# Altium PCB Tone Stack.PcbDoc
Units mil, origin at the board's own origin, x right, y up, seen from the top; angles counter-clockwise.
Board outline 3400 x 3400 mil, 2 copper layers (Top Layer, Bottom Layer); 39 components, 19 nets, 129 pads, 5 vias.
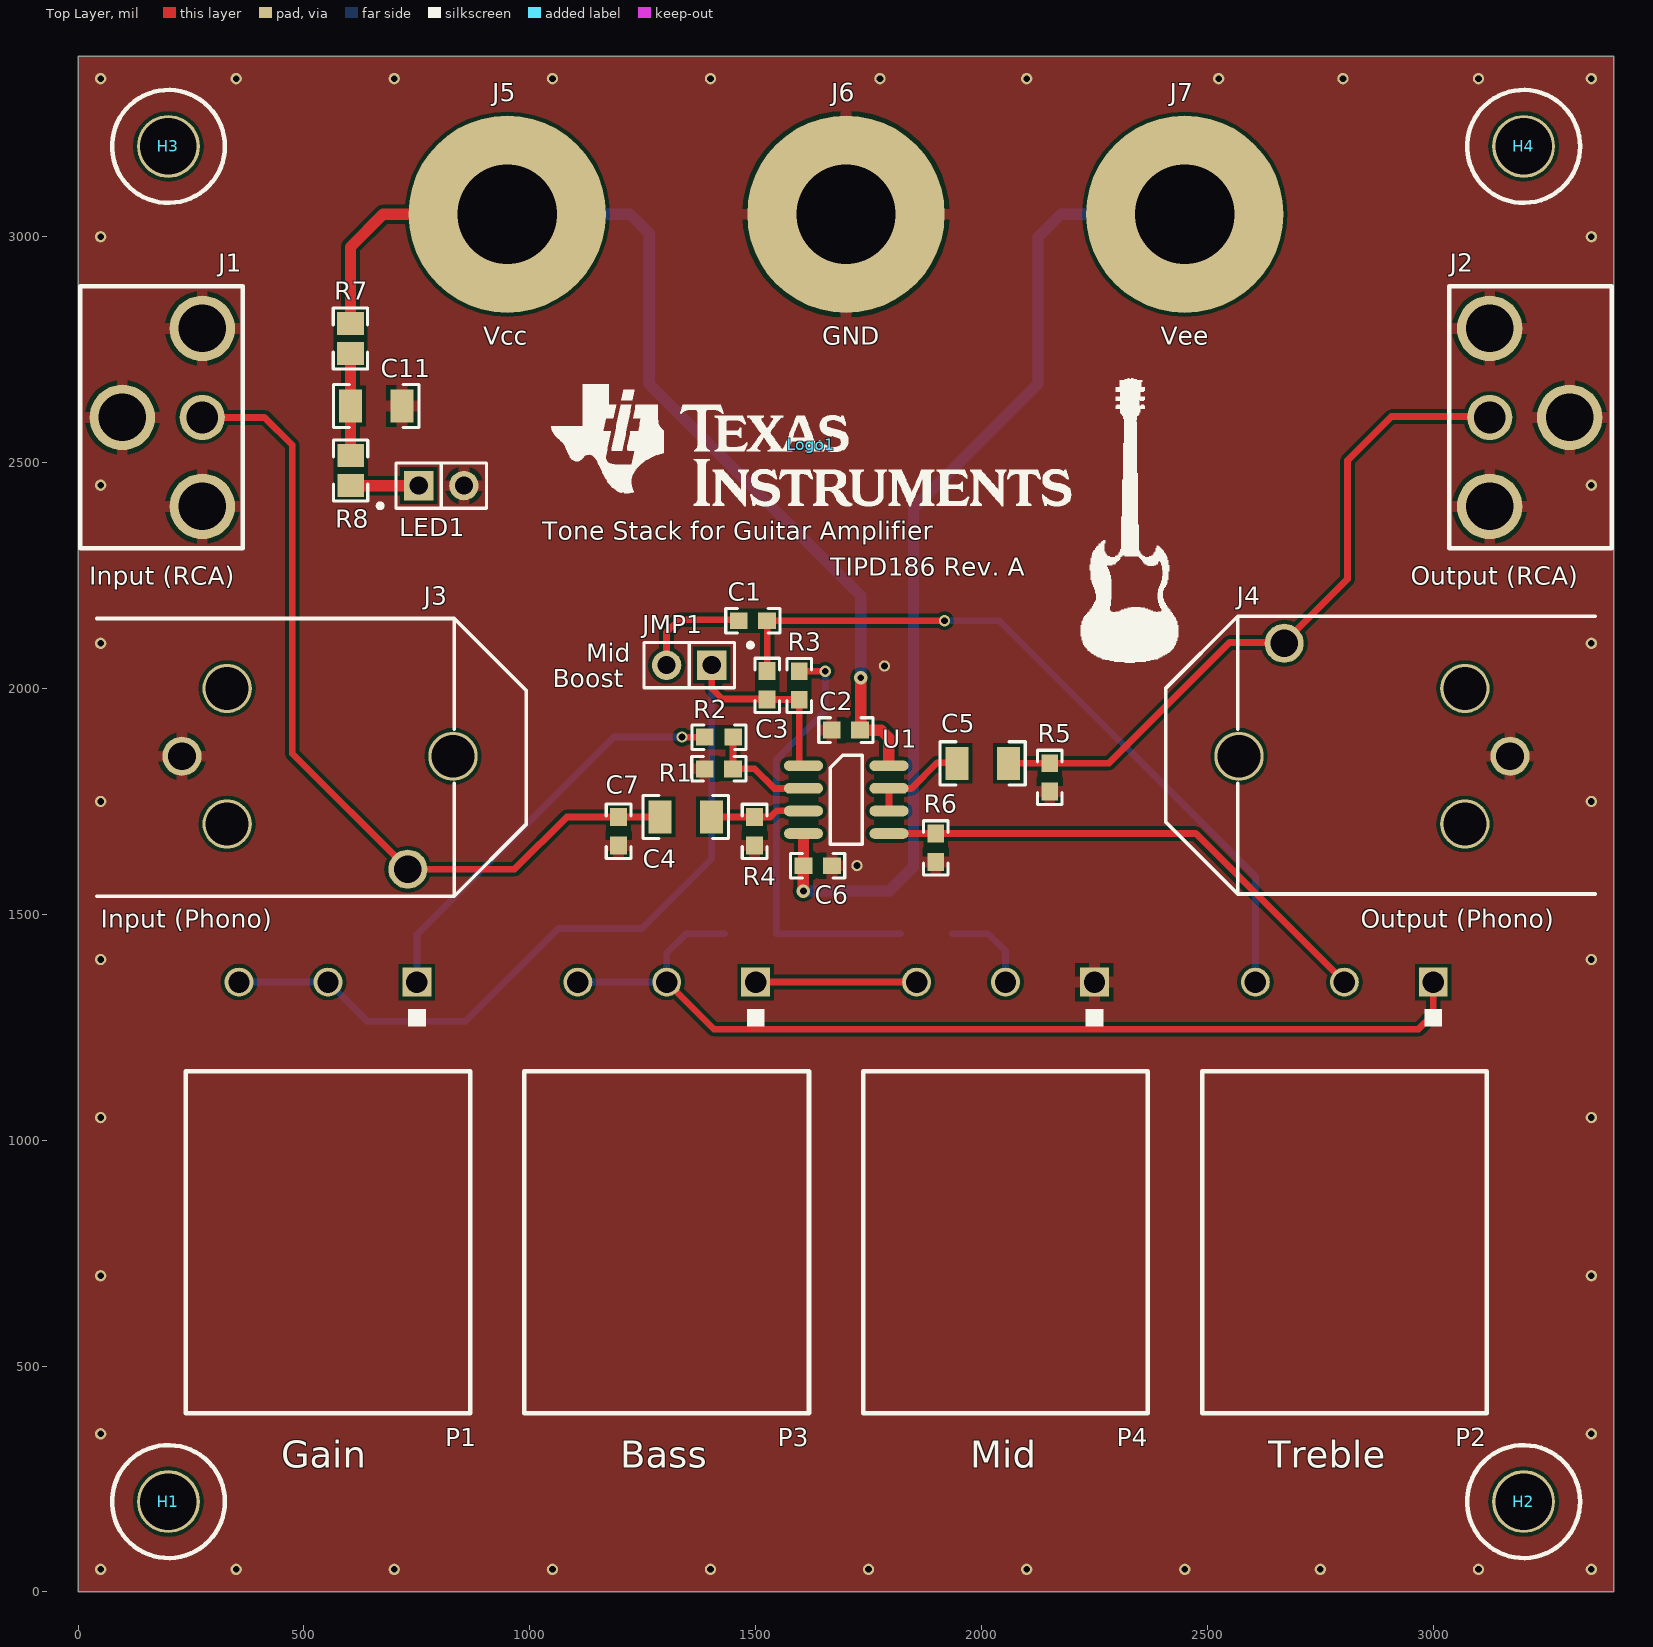
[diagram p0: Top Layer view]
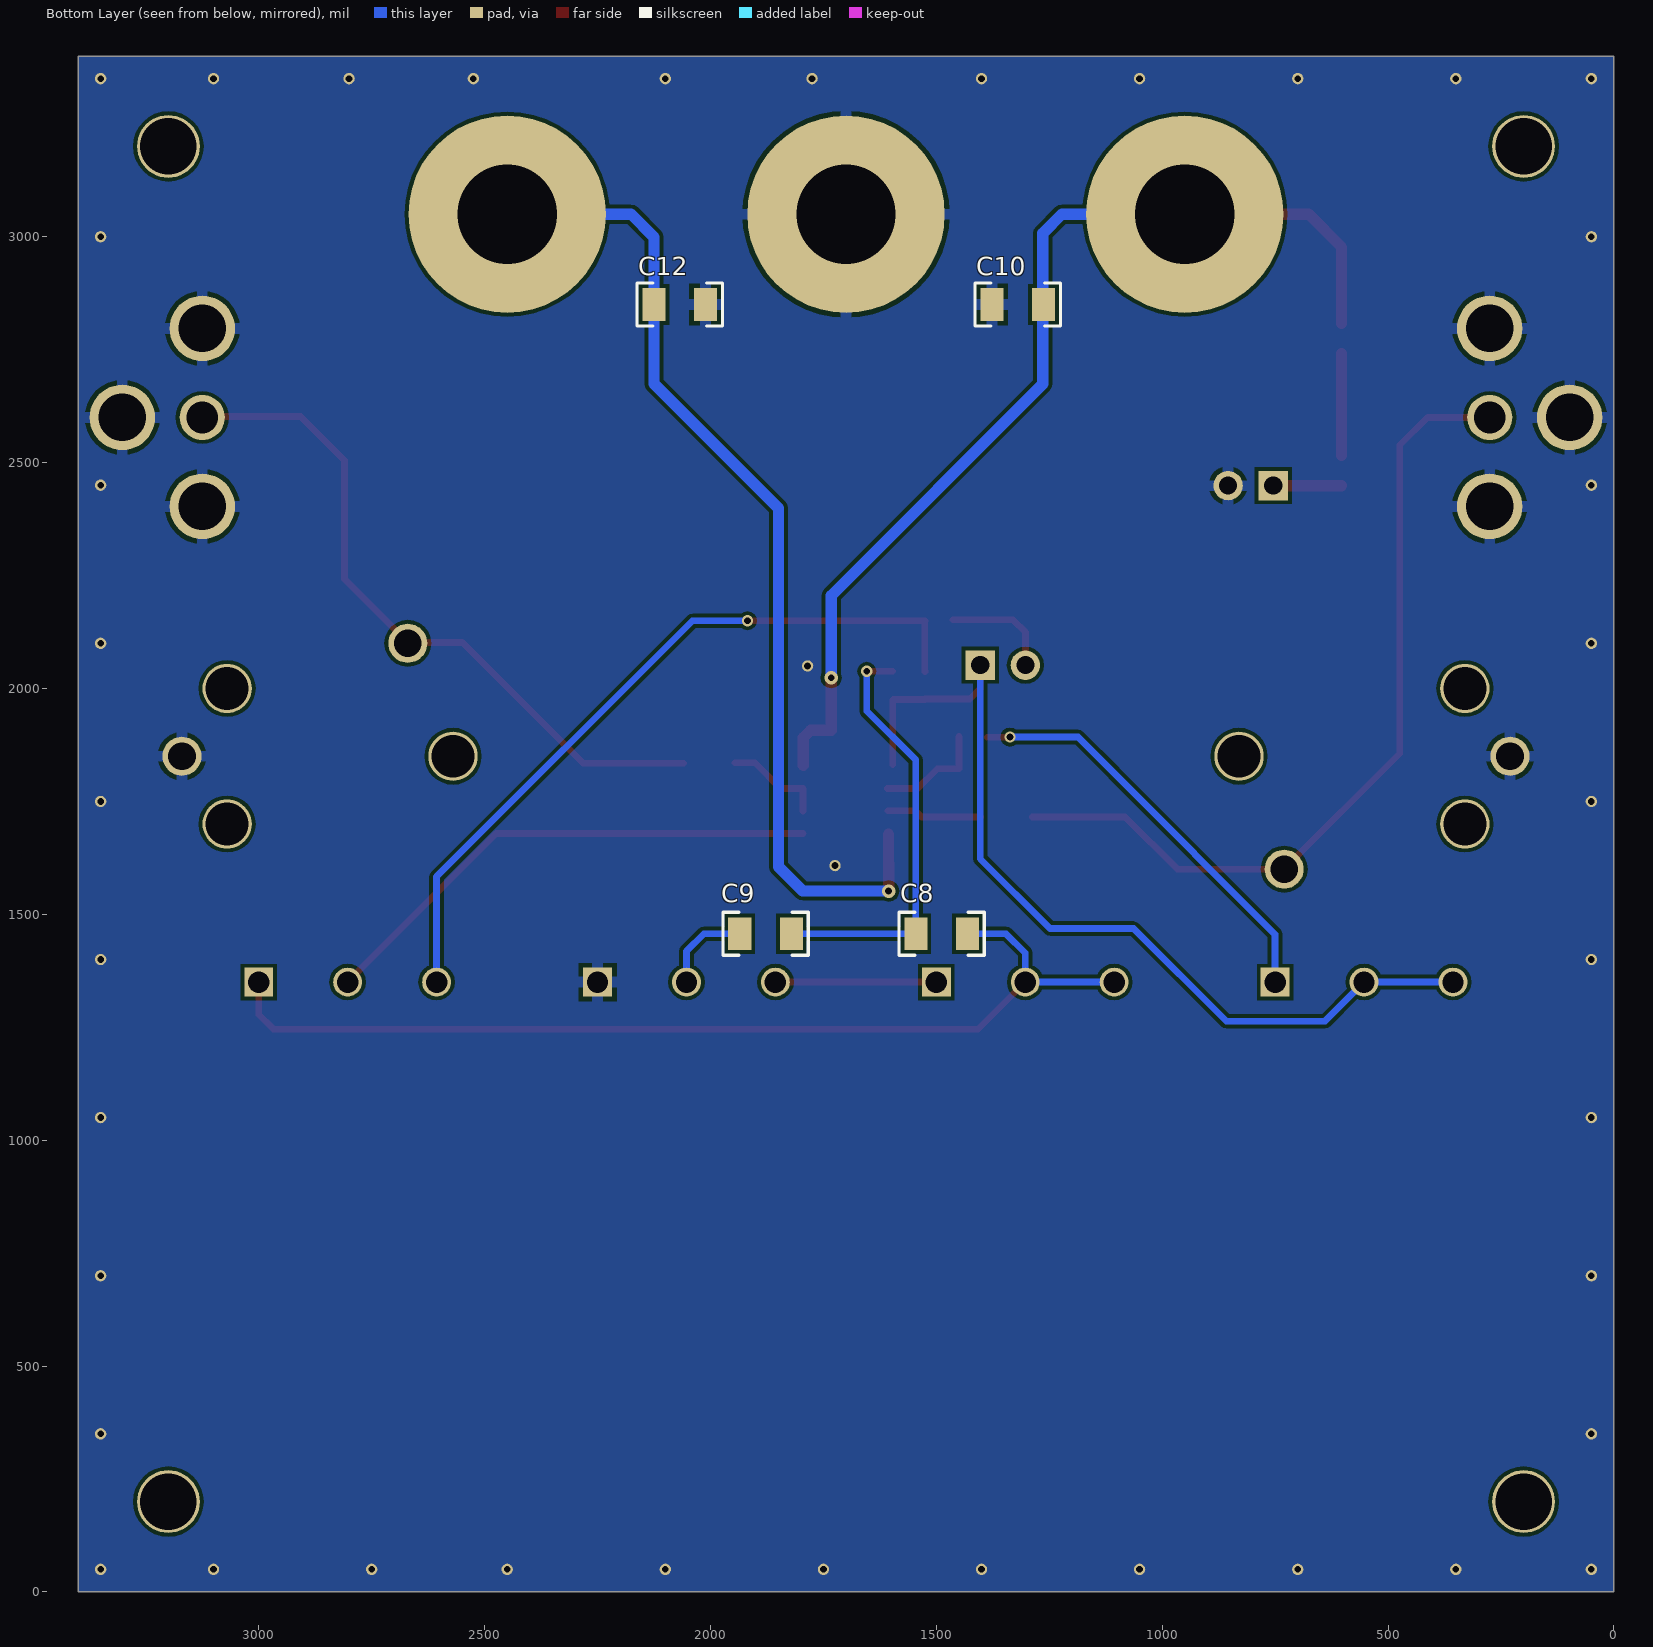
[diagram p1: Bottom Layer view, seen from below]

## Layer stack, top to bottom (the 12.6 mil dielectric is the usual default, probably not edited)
Top Layer: signal copper 1.4
Dielectric: core 12.6, FR-4, Dk 4.8
Bottom Layer: signal copper 1.4

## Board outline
0,0 0,3400 3400,3400 3400,0

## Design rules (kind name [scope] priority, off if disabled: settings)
AssemblyTestPointUsage [All] p1 off:
AssemblyTestpoint [All] p1 off: testpointundercomponent=TRUE minsize=40 maxsize=100 preferedsize=60 minholesize=0 maxholesize=40 preferedholesize=32 testpointgrid=1 usegrid=TRUE gridtolerance=0.01 allowsidetop=TRUE allowsidebottom=TRUE
Clearance [All] p1: gap=8
ComponentClearance [All] p1 off: gap=10 collisioncheckmode=3 verticalgap=10 showdistances=FALSE
DiffPairsRouting [All] p1 off: maxlimit=10 minlimit=10 mostfreqgap=10 maxuncoupledlength=500
FabricationTestPointUsage TestPointUsage [All] p1 off: valid=0 allowmultiple=FALSE
FabricationTestpoint Testpoint [All] p1 off: side=3 testpointundercomponent=TRUE minsize=40 maxsize=100 preferedsize=60 minholesize=0 maxholesize=40 preferedholesize=32 testpointgrid=1 allowsidetop=TRUE allowsidebottom=TRUE usegrid=TRUE gridtolerance=0.01
FanoutControl Fanout_BGA [IsBGA] p1 off: bgadir=Out bgaviamode=Centered fanoutstyle=Auto fanoutdirection=Alternating viagrid=1 // Fanout_BGA (Default Rule)
FanoutControl Fanout_LCC [IsLCC] p2 off: bgadir=Out bgaviamode=Centered fanoutstyle=Auto fanoutdirection=Alternating viagrid=1 // Fanout_LCC (Default Rule)
FanoutControl Fanout_SOIC [IsSOIC] p3 off: bgadir=Out bgaviamode=Centered fanoutstyle=Auto fanoutdirection=Alternating viagrid=1 // Fanout_SOIC (Default Rule)
FanoutControl Fanout_Small [(CompPinCount < 5)] p4 off: bgadir=Out bgaviamode=Centered fanoutstyle=Auto fanoutdirection=OutThenIn viagrid=1 // Fanout_Small (Default Rule)
FanoutControl Fanout_Default [All] p5 off: bgadir=Out bgaviamode=Centered fanoutstyle=Auto fanoutdirection=Alternating viagrid=1 // Fanout_Default (Default Rule)
Height [All] p1 off: minheight=0 maxheight=1000 prefheight=500
HoleSize [All] p1: absolutevalues=TRUE maxlimit=400 minlimit=15 maxpercent=80.000 minpercent=20.000
HoleToHoleClearance [All] p1: gap=7 allowstackedmicrovias=TRUE
MinimumAnnularRing [All] p1: minimumring=5
MinimumSolderMaskSliver [All] p1: minsoldermaskwidth=5
NetAntennae [All] p1 off: netantennaetolerance=0
PolygonConnect "GND Vias" [(InNet('GND') AND InPadClass('GND Vias'))] p1: connectstyle=Direct reliefconductorwidth=10 reliefentries=4 polygonreliefangle="90 Angle" airgapwidth=10
PolygonConnect [All] p2: connectstyle=Relief reliefconductorwidth=25 reliefentries=4 polygonreliefangle="90 Angle" airgapwidth=10
RoutingVias [All] p1: holewidth=10 width=25 viastyle="Through Hole" minholewidth=10 minwidth=25 maxholewidth=400 maxwidth=500
SilkToSilkClearance [All] p1: silktosilkclearance=5
SilkscreenOverComponentPads [All] p1: minsilkscreentomaskgap=5
SolderMaskExpansion [All] p1: expansion=4
Width [All] p1: maxlimit=100 minlimit=8 preferedwidth=15
10 further rules are at their usual default settings.

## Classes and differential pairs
pad class "GND Vias": Free-0
component class "Tone Stack": C1 C2 C3 C4 C5 C6 C7 C8 C9 C11 C12 H1 H2 H3 H4 J1 J2 J3 J4 J5 J6 J7 LED1 Logo1 P1 P2 P3 P4 R1 R2 R3 R4 R5 R6 R8 U1

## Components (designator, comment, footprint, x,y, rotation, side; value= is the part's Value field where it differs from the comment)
C1 "Used in BOM report" 0603 1493.9,2150 r0 top
C2 "Used in BOM report" 0603 1699.73,1907.86 r180 top
C3 "Used in BOM report" 0603 1525.45,2006.96 r90 top
C4 "Used in BOM report" 1206 1345.21,1715.66 r180 top
C5 "Used in BOM report" 1206 2002.47,1834.31 r180 top
C6 "Used in BOM report" 0603 1637.39,1607.67 r0 top
C7 "Used in BOM report" 0603 1196.48,1683.96 r270 top
C8 "Used in BOM report" 1206 1488.37,1457 r180 bottom
C9 "Used in BOM report" 1206 1878.12,1457 r0 bottom
C10 "Used in BOM report" 1206 1319.89,2850 r0 bottom
C11 "Used in BOM report" 1206 660.3,2625.39 r0 top
C12 "Used in BOM report" 1206 2067.98,2850 r0 bottom
H1 "Standoff, 1\", 4-40, Alum, F-F" "STANDOFF HEX 4-40THR ALUM 1\"L" 200,200 r0 top
H2 "Standoff, 1\", 4-40, Alum, F-F" "STANDOFF HEX 4-40THR ALUM 1\"L" 3200,200 r0 top
H3 "Standoff, 1\", 4-40, Alum, F-F" "STANDOFF HEX 4-40THR ALUM 1\"L" 200,3200 r0 top
H4 "Standoff, 1\", 4-40, Alum, F-F" "STANDOFF HEX 4-40THR ALUM 1\"L" 3200,3200 r0 top
J1 "Input (RCA)" RCJ-01X 275,2600 r90 top
J2 "Output (RCA)" RCJ-01X 3125,2600 r270 top
J3 "Input (Phono)" Switchcraft_RN111PC 330,1850 r180 top
J4 "Output (Phono)" Switchcraft_RN111PC 3070,1850 r0 top
J5 "Vcc" "JACK NON-INSULATED .218\"" 950,3050 r90 top
J6 "GND" "JACK NON-INSULATED .218\"" 1700,3050 r90 top
J7 "Vee" "JACK NON-INSULATED .218\"" 2450,3050 r90 top
JMP1 "Mid" "Header 100mil, 1x2" 1352.84,2051.54 r180 top
LED1 "XREBLU-L1-R250-00K01" "Header 100mil, 1x2" 804.16,2448.98 r0 top
Logo1 "Texas Instruments" TI_Stacked_Overlay_Medium 1623.42,2539.34 r0 top
P1 "Gain" POT_RV16 750,1350 r180 top
P2 "Treble" POT_RV16 3000,1350 r180 top
P3 "Bass" POT_RV16 1500,1350 r180 top
P4 "Mid" POT_RV16 2250,1350 r180 top
R1 "Used in BOM report" 0603 1418.61,1822.13 r180 top
R2 "Used in BOM report" 0603 1418.97,1892.23 r0 top
R3 "Used in BOM report" 0603 1596.55,2006.69 r270 top
R4 "Used in BOM report" 0603 1497.57,1683.7 r270 top
R5 "Used in BOM report" 0603 2150.98,1803.13 r90 top
R6 "Used in BOM report" 0603 1898.69,1647.2 r90 top
R7 "Used in BOM report" 0805 602.99,2774.69 r270 top
R8 "Used in BOM report" 0805 603.31,2482.44 r270 top
U1 "OPA1652AID" D0008A_N 1700.54,1753.87 r0 top

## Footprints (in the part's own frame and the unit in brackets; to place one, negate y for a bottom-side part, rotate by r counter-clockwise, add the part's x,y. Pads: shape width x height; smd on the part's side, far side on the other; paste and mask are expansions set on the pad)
0603 [mm] "0603 from SM-752 data"
  rect 1x0.95 smd: 1(-0.8,0) 2(0.8,0)
  silkscreen extent -1.52,-0.69 1.52,0.69, body extent -0.87,-0.47 0.87,0.47, height 0.85
0805 [mm] "0805 from SM-752 data"
  rect 1.3x1.5 smd: 1(-0.85,0) 2(0.85,0)
  silkscreen extent -1.72,-0.97 1.72,0.97, body extent -1.1,-0.72 1.1,0.72, height 1.1
1206 [mm] "1206 from SM-752 data"
  rect 1.3x1.85 smd: 1(-1.45,0) 2(1.45,0)
  silkscreen extent -2.4,-1.21 2.4,1.21, body extent -1.7,-0.9 1.7,0.9, height 1.35
D0008A_N [mm] "SOIC, 8-Leads, Body 4.9x3.9mm, Pitch 1.27mm, IPC Medium Density"
  oval 2.2x0.6 smd: 1(-2.4,1.905) 2(-2.4,0.635) 3(-2.4,-0.635) 4(-2.4,-1.905) 5(2.4,-1.905) 6(2.4,-0.635) 7(2.4,0.635) 8(2.4,1.905)
  silkscreen extent -0.9,-2.5 0.9,2.5, body extent -3,-2.45 3,2.45, height 1.63
"Header 100mil, 1x2" [mm] "Header 100mil, 1x2"
  rect 1.65x1.65 hole 1.016 mask+0: 1(-1.27,0)
  round 1.65 hole 1.016 mask+0: 2(1.27,0)
  silkscreen extent -3.57,-1.27 2.54,1.27, body extent -2.54,-1.27 2.54,1.27, height 8.38
"JACK NON-INSULATED .218\"" [mil] "JACK NON-INSULATED .218\""
  round 437 hole 220: 1(0,0)
POT_RV16 [mil] "Pot, Right-Angle PC Mount"
  rect 64x64 hole 47.24: 1(0,0)
  round 64 hole 47.24: 2(196.85,0) 3(393.7,0)
  silkscreen extent -118,59 512,955, body extent -113,-20 507,950, height 982
RCJ-01X [mil] "RCA Jack, Metal, Right Angle, PCB Mount"
  round 145 hole 105: 1(0,177) 3(197,0) 4(-197,0)
  round 100 hole 70: 2(0,0)
  silkscreen extent -290,-90 290,270, body extent -230,-55 227,515, height 485
"STANDOFF HEX 4-40THR ALUM 1\"L" [mil] "STANDOFF HEX 4-40THR ALUM 1\"L"
  round 139 hole 125: 0(0,0)
  silkscreen extent -125,-125 125,125
Switchcraft_RN111PC [mil] "Switchcraft"
  round 86.61 hole 61.02 unplated: 1(-400,250) 2(100,0)
  round 109 hole 95 unplated: MH1(-500,0) MH2(0,150) MH3(0,-150)
  silkscreen extent -662,-305 289,310, body extent -660,-305 598,310, height 680
TI_Stacked_Overlay_Medium [mil]
  silkscreen extent -576,-136 576,134

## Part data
C1 C2 C3 C4 C5 C6 C7 C8 C9 C10 C11 C12: library part Capacitor, "CAP, CERM, xxxF, xxV, [TempCo], xx%, [PackageReference]"
H1 H2 H3 H4: "STANDOFF HEX 4-40THR ALUM 1\"L"
J1 J2: library part RCJ-011, "RCA Jack, Metal, Right Angle"
J3 J4: library part RN111PC, "Phone Jack, 1/4\", R/A, TH"
J5 J6 J7: library part "Banana Jack, Solder", "JACK NON-INSULATED .218\""
JMP1: library part CHS-01TB, "Switch, Slide, SPST, Top Slide, SMT"
LED1: "LED, Blue, SMD"
Logo1: library part TI_Logo, "Texas Instrument Corporate Signature"
P1 P2 P3 P4: library part POT_CT-9WXXXYYY, "Potentiometer, Single Slide,  xxOhms, 0.1W, 20%"
R1 R2 R3 R4 R5 R6 R7 R8: library part Resistor, "RES, xxx ohm, x%, xW, [PackageReference]"
U1: "Sound Plus Low Noise and Distortion, General-Purpose, FET-Input Audio Operational Amplifier, 4.5 to 36 V, -40 to 85 degC, 8-pin SOIC (D0008A), Green (RoHS & no Sb/Br)"

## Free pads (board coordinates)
  round 25 hole 15: 0(50,50) 0(50,350) 0(50,700) 0(50,1050) 0(50,1400) 0(50,1750) 0(50,2100) 0(50,2450) 0(50,3000) 0(50,3350) 0(350,50) 0(350,3350) 0(700,50) 0(700,3350) 0(1050,50) 0(1050,3350) 0(1400,50) 0(1400,3350) 0(1724.16,1607.86) 0(1750,50) 0(1775,3350) 0(1785,2050) 0(2100,50) 0(2100,3350) 0(2450,50) 0(2525,3350) 0(2750,50) 0(2800,3350) 0(3100,50) 0(3100,3350) 0(3350,50) 0(3350,350) 0(3350,700) 0(3350,1050) 0(3350,1400) 0(3350,1750) 0(3350,2100) 0(3350,2450) 0(3350,3000) 0(3350,3350)

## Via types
v1: diameter 25, hole 15, Top Layer to Bottom Layer, 3 vias
v2: diameter 30, hole 15, Top Layer to Bottom Layer, 2 vias

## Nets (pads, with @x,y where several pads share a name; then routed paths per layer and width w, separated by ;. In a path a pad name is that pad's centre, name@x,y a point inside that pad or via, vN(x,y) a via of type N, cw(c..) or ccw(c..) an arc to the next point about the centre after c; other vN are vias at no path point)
GND: C2.2 C6.2 C7.2 C10.2 C11.2 C12.1 J1.1 J1.3 J1.4 J2.1 J2.3 J2.4 J3.2 J4.2 J6.1 LED1.2 P4.1 pad.0 R1.2 R4.2 R5.1 R6.1
NetC1_1: C1.1 JMP1.2 | length 244.8
  Top Layer w15: JMP1.2 1302.84,2124.64 1330.17,2151.96 C1.1@1463.25,2151.96
NetC1_2: C1.2 C3.2 P2.3 | length 1662
  Top Layer w15: C3.2@1525.39,2036.96 C3.2 ; C1.2 v1(1918.02,2150) ; C3.2 C1.2
  Bottom Layer w15: v1(1918.02,2150) 2039.65,2150 2606.3,1583.35 P2.3
NetC3_1: C3.1 JMP1.1 P1.2 P1.3 R3.2 U1.1 | length 2058
  Top Layer w15: JMP1.1 1402.84,1999.88 1426.01,1976.72 C3.1@1525.47,1976.72 ; C3.1 R3.2@1595.51,1975.46 ; U1.1@1596.55,1830.93 R3.2
  Bottom Layer w15: P1.3 P1.2 639.59,1263.56 858.26,1263.56 1063.07,1468.37 1248.29,1468.37 1402.84,1622.93 JMP1.1
NetC4_1: C4.1 R4.1 U1.3 | length 210.7
  Top Layer w15: C4.1 R4.1@1497.11,1715.66 ; R4.1 1532.42,1715.2 1546.52,1729.29 U1.3@1607.61,1729.29
NetC4_2: C4.2 C7.1 J1.2 J3.1 | length 1875
  Top Layer w15: J1.2 412.95,2600 474.13,2538.82 474.13,1855.87 J3.1 966.6,1600 1082.05,1715.45 C7.1 C4.2@1287.92,1715.45
NetC5_1: C5.1 J2.2 J4.1 R5.2 | length 1535.4
  Top Layer w15: C5.1 R5.2@2148.82,1834.31 ; R5.2 2282.02,1834.63 2548.92,2101.52 J4.1@2670,2101.52 ; J4.1 J4.1@2670,2101.52 ; J2.2@3123.69,2601.85 2907.16,2601.85 2810.44,2505.13 2810.44,2241.96 J4.1@2670,2101.52
NetC5_2: C5.2 U1.6 U1.7 | length 224.5
  Top Layer w15: U1.6 U1.7@1795.03,1778.56 ; U1.7 1845.03,1778.87 1901.97,1835.81 C5.2@1946.23,1835.81
NetC8_1: C8.1 C9.1 R3.1 | length 959.3
  Top Layer w15: R3.1 v1(1654.1,2038.18)
  Bottom Layer w15: C8.1 C8.1 ; v1(1654.1,2038.18) 1654.1,1950.02 1545.5,1841.43 C8.1 ; C9.1 C8.1
NetC8_2: C8.2 P2.1 P3.2 P3.3 | length 2232.2
  Top Layer w15: P3.2 1407.3,1245.85 2967.38,1245.85 3000,1278.47 P2.1
  Bottom Layer w15: P3.3 P3.2 1303.15,1414.68 1345.38,1456.91 C8.2@1431.28,1456.91
NetC9_2: C9.2 P4.2 | length 202.3
  Bottom Layer w15: C9.2 2014.52,1457 2053.15,1418.37 P4.2
NetC11_1: C11.1 R7.2 R8.1 | length 218
  Top Layer w25: C11.1@602.99,2632.65 R7.2 ; R8.1@603.21,2516 C11.1
NetLED1_1: LED1.1 R8.2 | length 150.8
  Top Layer w25: R8.2 LED1.1
NetP1_1: P1.1 R2.1 | length 924.5
  Top Layer w15: v1@1336.95,1892.23 R2.1
  Bottom Layer w15: P1.1 750,1455.86 1106.64,1812.5 1106.64,1813.03 1185.99,1892.39 v1(1336.95,1892.39)
NetP2_2: P2.2 R6.2 U1.5 | length 1145
  Top Layer w15: U1.5 R6.2@1899.39,1678.87 ; R6.2 2474.45,1678.7 P2.2
NetP3_1: P3.1 P4.3 | length 356.3
  Top Layer w15: P3.1 P4.3
NetR1_1: R1.1 R2.2 U1.2 | length 248.2
  Top Layer w15: R2.2@1450.11,1893.91 R1.1 1497.96,1822.13 1541.38,1778.72 U1.2@1608.59,1778.72
VCC: C2.1 C10.1 J5.1 R7.1 U1.8 | length 2300.4
  Top Layer w25: R7.1 602.99,2977.39 675.6,3050 J5.1 ; C2.1@1732.76,1907.86 1777.84,1907.86 1794.93,1890.77 U1.8@1794.93,1830.36 ; C2.1@1732.76,1909.3 v2(1732.76,2023.98)
  Bottom Layer w25: J5.1 1222.03,3050 1264.53,3007.5 1264.53,2673.86 1732.34,2206.05 v2@1732.34,2023.66
VEE: C6.1 C12.2 J7.1 U1.4 | length 2250.1
  Top Layer w25: v2(1605.67,1551.58) C6.1@1605.67,1607.44 ; C6.1@1605.67,1607.67 C6.1@1605.67,1612.28 ; C6.1 U1.4@1605.9,1677.29
  Bottom Layer w25: v2(1605.67,1551.58) 1795.79,1551.58 1849.54,1605.33 1849.54,2399.09 2125.07,2674.61 C12.2 2125.07,2999.05 2176.01,3050 J7.1
pads on no net: H1.0 H2.0 H3.0 H4.0 J3.MH1 J3.MH2 J3.MH3 J4.MH1 J4.MH2 J4.MH3

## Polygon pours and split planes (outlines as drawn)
GND on Top Layer "Top Layer-No Net 1" (solid, remove dead copper, pour order 4): 0,0 3400,0 3400,3400 0,3400
GND on Bottom Layer "Bottom Layer-No Net" (solid, remove dead copper, pour order 6): 0,0 3400,0 3400,3400 0,3400

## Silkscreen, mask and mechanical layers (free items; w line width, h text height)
Top Overlay:
  drawing of 427 lines, arcs and shapes, not listed
  text "Tone Stack for Guitar Amplifier" at 1027.24,2328.76 h40
  text "TIPD186 Rev. A" at 1664.91,2249.23 h40
  text "Boost" at 1051.03,2003.26 h40
Mechanical 1:
  lines w10: -370,60 -350,0 ; -370,3340 -350,3400 ; -360,0 -340,0 ; -360,3400 -340,3400 ; -350,1419.09 -350,0 ; -350,1980.91 -350,3400 ; -330,60 -350,0 ; -330,3340 -350,3400 ; 0,-160 0,-140 ; 60,-170 0,-150 ; 60,-130 0,-150 ; 1419.09,-150 0,-150 ; 1980.91,-150 3400,-150 ; 3340,-170 3400,-150 ; 3340,-130 3400,-150 ; 3400,-160 3400,-140
  text "3400 (mil)" at -314.01,1429.09 h60 r90
  text "3400 (mil)" at 1429.09,-185.99 h60
Mechanical 13:
  lines w10: -20,60 0,0 ; -20,3340 0,3400 ; -10,0 10,0 ; -10,3400 10,3400 ; 0,1499.06 0,0 ; 0,1900.94 0,3400 ; 20,60 0,0 ; 20,3340 0,3400
  text "3400mil" at 35.99,1509.06 h60 r90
